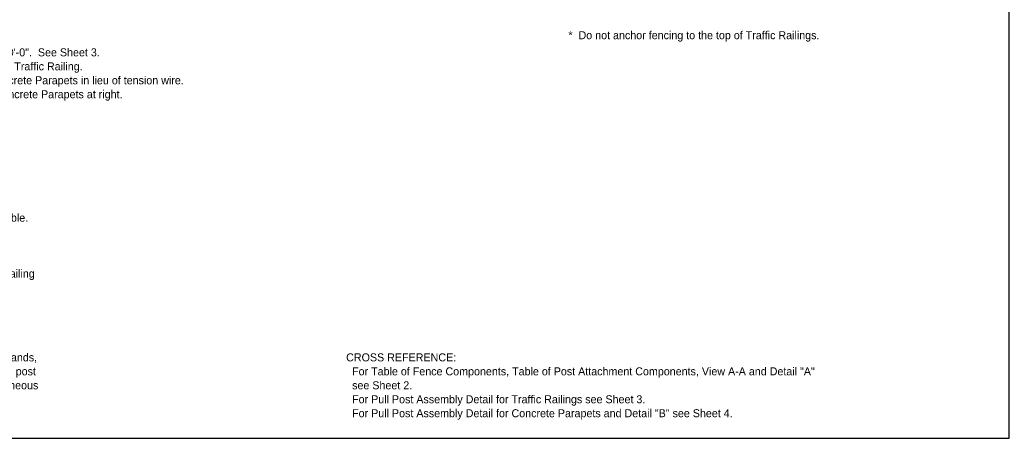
# Model space of a CAD drawing. Extents: x 0 to 72.1, y -15.2 to 30.1.
# Drawn here: x 16.14 to 41.07, y 2.05 to 12.6 of the extents above; entities that cross this region are included whole.
import ezdxf

# ---------------------------------------------------------------- set-up
doc = ezdxf.new("R2010")
doc.units = 0
doc.layers.add('ActivePts-ConstElements', color=7, linetype='Continuous')
doc.layers.add('PlotBorder_dp', color=7, linetype='Continuous')

msp = doc.modelspace()

# ---------------------------------------------------------------- linework, layer by layer
at = {"layer": 'ActivePts-ConstElements'}
msp.add_lwpolyline([(0.016, 2.054), (41.067, 2.054), (41.067, 28), (0.016, 28)], close=True, dxfattribs=at)

# ---------------------------------------------------------------- texts
at = {"layer": 'PlotBorder_dp'}
for s, p in [('*  Do not anchor fencing to the top of Traffic Railings.', (29.963, 12.111)), ('  1.  A Pull Post Assembly is required at maximum intervals of 500\'-0".  See Sheet 3.', (8.122, 11.679)), ('  2.  Brace rails are only required for vertical fence installations on Traffic Railing.  ', (8.122, 11.327)), ('  3.  Provide horizontal rails for vertical fence installations on Concrete Parapets in lieu of tension wire.  ', (8.122, 10.975)), ('      Locate horizontal rails as shown in the Typical Section for Concrete Parapets at right.', (8.122, 10.623)), ('CROSS REFERENCE:', (24.364, 3.991)), ('  For Table of Fence Components, Table of Post Attachment Components, View A-A and Detail "A"', (24.364, 3.639)), ('  see Sheet 2.', (24.364, 3.287)), ('  For Pull Post Assembly Detail for Traffic Railings see Sheet 3.', (24.364, 2.935)), ('  For Pull Post Assembly Detail for Concrete Parapets and Detail "B" see Sheet 4.', (24.364, 2.583))]:
    msp.add_text(s, height=0.2016, dxfattribs=at).set_placement(p)
for s, p in [('  thickness of shim plates will be determined in the field.  Install chain link fence in accordance with ASTM F567 as applicable.', (1.385, 7.511)), ('  See Index 521-820 - Pedestrian/Bicycle Railing for Concrete Parapet details.  Provide fencing in lieu of aluminum bullet railing ', (1.385, 6.103)), ('  Payment will be made under Fencing, Type R.  Payment includes posts, horizontal and expansion rails, brace rails and bands,', (1.385, 3.991)), ('  rail ends, combination rail ends, boulevard clamps, chain link fabric, tension wire, ties, hog rings, tension bars and bands, post', (1.385, 3.639)), ('  and loop caps, pipe clamps, base plates, anchor rods, bolts, nuts, washers, shim plates, spacers, bearing pads, miscellaneous', (1.385, 3.287))]:
    msp.add_text(s, height=0.2016, rotation=0, dxfattribs=at).set_placement(p)

doc.saveas('drawing.dxf')
